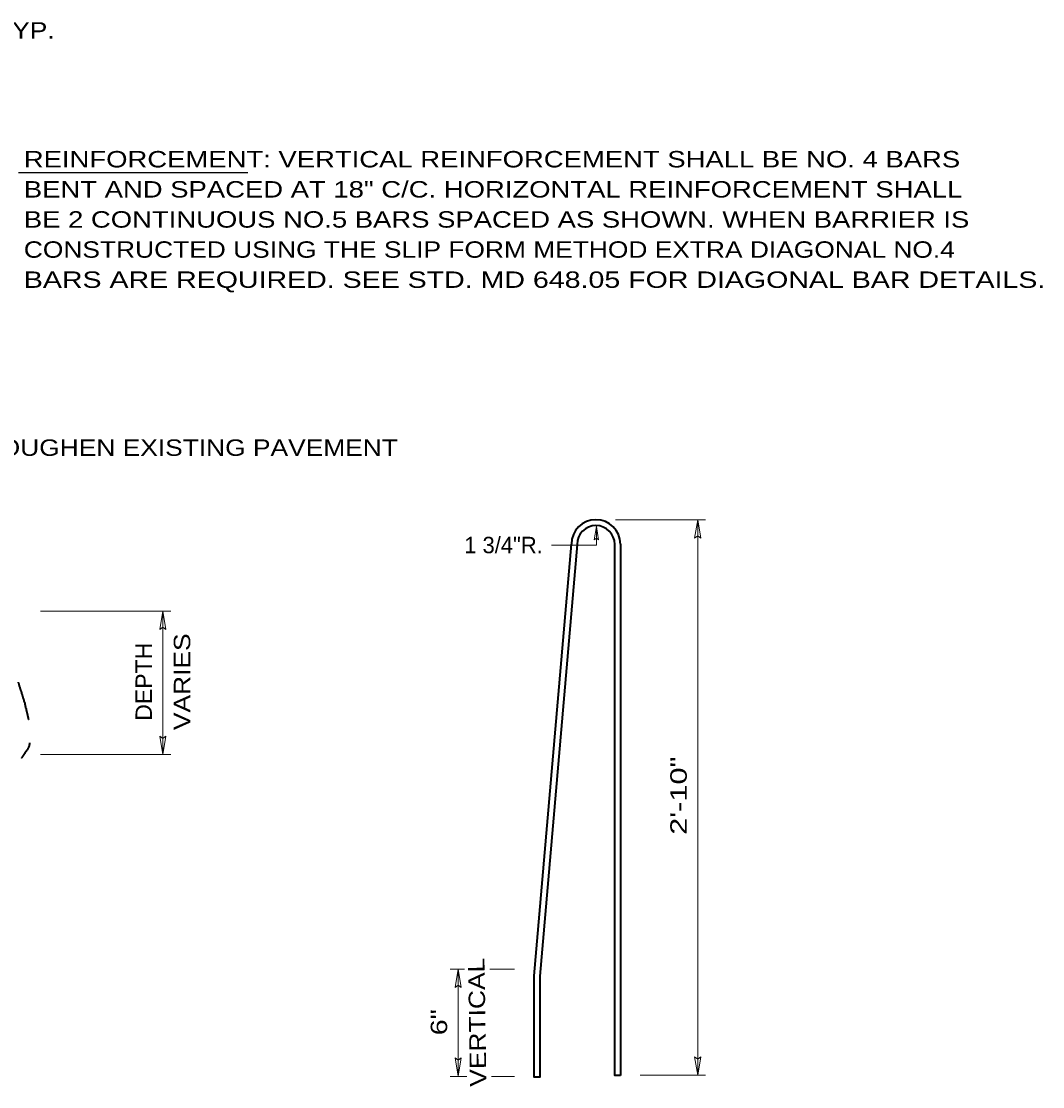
# Model space of a CAD drawing. Extents: x 2.21 to 9.21, y 11.59 to 21.05.
# Drawn here: x 5.477 to 9.21, y 16.167 to 20.059 of the extents above; entities that cross this region are included whole.
import ezdxf
from ezdxf.enums import TextEntityAlignment as Align

# ---------------------------------------------------------------- set-up
doc = ezdxf.new("R2010")
doc.units = 0
doc.header["$LTSCALE"] = 0.024
doc.linetypes.add('LONG_DASHED', pattern=[7.5, 6, -1.5])
for name, color, linetype, lineweight in [('1', 7, 'Continuous', 35), ('10', 7, 'Continuous', 13), ('12', 7, 'Continuous', 53)]:
    doc.layers.add(name, color=color, linetype=linetype, lineweight=lineweight)

msp = doc.modelspace()

# ---------------------------------------------------------------- linework, layer by layer
at = {"layer": '1'}
for p, q in [((7.35233, 16.57133), (7.488, 18.14917)), ((7.66683, 18.14917), (7.66683, 16.208))]:
    msp.add_line(p, q, dxfattribs=at)
for points in [[(7.50867, 18.14833), (7.373, 16.57083), (7.373, 16.201)], [(7.66683, 16.20717), (7.64617, 16.20717), (7.64617, 18.14833)], [(7.373, 16.2015), (7.35233, 16.2015), (7.35233, 16.57133)]]:
    msp.add_lwpolyline(points, dxfattribs=at)
for centre, radius in [((7.57745, 18.14914), 0.08937), ((7.57745, 18.14829), 0.06877)]:
    msp.add_arc(centre, radius, 0, 180, dxfattribs=at)
at = {"layer": '10', "lineweight": 25}
msp.add_line((5.46717, 19.5075), (6.30483, 19.5075), dxfattribs=at)
at = {"layer": '10'}
for p, q in [((7.6495, 18.23817), (7.97817, 18.23817)), ((7.93817, 18.17083), (7.9495, 18.23817)), ((7.9495, 18.23817), (7.9495, 16.20917)), ((7.96067, 18.17083), (7.9495, 18.23817)), ((7.57117, 18.16517), (7.57917, 18.21317)), ((7.58717, 18.16517), (7.57917, 18.21317)), ((7.93817, 18.17083), (7.9495, 18.17933)), ((7.96067, 18.17083), (7.9495, 18.17933)), ((7.57117, 18.16517), (7.57917, 18.17117)), ((7.58717, 18.16517), (7.57917, 18.17117)), ((5.548, 17.90433), (6.0235, 17.90433)), ((5.9835, 17.83717), (5.99467, 17.90433)), ((5.99467, 17.90433), (5.99467, 17.38)), ((6.006, 17.83717), (5.99467, 17.90433)), ((5.9835, 17.83717), (5.99467, 17.8455)), ((6.006, 17.83717), (5.99467, 17.8455)), ((5.9835, 17.44717), (5.99467, 17.38)), ((5.9835, 17.44717), (5.99467, 17.43883)), ((6.006, 17.44717), (5.99467, 17.38)), ((6.006, 17.44717), (5.99467, 17.43883)), ((5.548, 17.38), (6.0235, 17.38)), ((7.09683, 16.59633), (7.04483, 16.59633)), ((7.0625, 16.52917), (7.07367, 16.59633)), ((7.07367, 16.59633), (7.07367, 16.20533)), ((7.08483, 16.52917), (7.07367, 16.59633)), ((7.28033, 16.59633), (7.19017, 16.59633)), ((7.0625, 16.52917), (7.07367, 16.5375)), ((7.08483, 16.52917), (7.07367, 16.5375)), ((7.0625, 16.2725), (7.07367, 16.20533)), ((7.0625, 16.2725), (7.07367, 16.264)), ((7.08483, 16.2725), (7.07367, 16.20533)), ((7.08483, 16.2725), (7.07367, 16.264)), ((7.93817, 16.27633), (7.9495, 16.20917)), ((7.93817, 16.27633), (7.9495, 16.26783)), ((7.96067, 16.27633), (7.9495, 16.20917)), ((7.96067, 16.27633), (7.9495, 16.26783)), ((7.106, 16.204), (7.04483, 16.204)), ((7.28033, 16.204), (7.19633, 16.204)), ((7.73883, 16.20917), (7.97817, 16.20917))]:
    msp.add_line(p, q, dxfattribs=at)
msp.add_lwpolyline([(7.415, 18.14583), (7.57917, 18.14583), (7.57917, 18.21317)], dxfattribs=at)
at = {"layer": '10', "linetype": 'LONG_DASHED', "lineweight": 35}
for points in [[(5.466, 17.64517), (5.466, 17.64367), (5.467, 17.64067), (5.4675, 17.63967), (5.468, 17.63817), (5.468, 17.63667), (5.4685, 17.63517), (5.46883, 17.63417), (5.46983, 17.63133), (5.46983, 17.62983), (5.47083, 17.62733), (5.47183, 17.62433), (5.47267, 17.621), (5.47317, 17.61933), (5.47417, 17.6175), (5.47517, 17.614), (5.476, 17.6125), (5.477, 17.6095), (5.4775, 17.6075), (5.478, 17.6045), (5.4785, 17.60267), (5.48033, 17.59817), (5.48083, 17.59617), (5.48133, 17.59467), (5.48183, 17.59267), (5.48233, 17.59117), (5.48317, 17.58883), (5.48317, 17.58783), (5.48367, 17.58633), (5.48467, 17.58433), (5.48517, 17.58283), (5.48517, 17.58133), (5.48617, 17.57983), (5.48617, 17.57833), (5.488, 17.5725), (5.489, 17.57), (5.49, 17.5675), (5.49, 17.5655), (5.4905, 17.564), (5.49083, 17.562), (5.49133, 17.5605), (5.49133, 17.55917), (5.49183, 17.55667), (5.49283, 17.55517), (5.49283, 17.55317), (5.49333, 17.54967), (5.49467, 17.54767), (5.49467, 17.54633), (5.49517, 17.54483), (5.49567, 17.54133), (5.49617, 17.54033), (5.49667, 17.53733), (5.49717, 17.53583), (5.49767, 17.5325), (5.4985, 17.531), (5.4985, 17.5295), (5.499, 17.527), (5.5, 17.524), (5.5, 17.52267), (5.50133, 17.51817), (5.50133, 17.51617), (5.50183, 17.51517), (5.50183, 17.51417), (5.50233, 17.51267), (5.50233, 17.51117), (5.50283, 17.50933), (5.50333, 17.50833), (5.50283, 17.50783), (5.50383, 17.50633), (5.50383, 17.50483), (5.50433, 17.50333), (5.50433, 17.50183), (5.50517, 17.49883), (5.50483, 17.4975), (5.50567, 17.4945), (5.50617, 17.4935), (5.50617, 17.4925), (5.50667, 17.491), (5.50667, 17.48317), (5.50717, 17.48167), (5.50717, 17.46983), (5.50767, 17.4685), (5.50767, 17.4625), (5.508, 17.461), (5.508, 17.45267), (5.5085, 17.45117), (5.5085, 17.44783), (5.508, 17.44483), (5.5085, 17.44333), (5.5085, 17.44033), (5.5085, 17.4325), (5.508, 17.43117), (5.5085, 17.42967), (5.5085, 17.42817), (5.508, 17.42667), (5.508, 17.42467), (5.50767, 17.42333)], [(5.50767, 17.42333), (5.50767, 17.42183), (5.50717, 17.41983), (5.50717, 17.41833), (5.50617, 17.4155), (5.50617, 17.414), (5.50417, 17.40817), (5.50283, 17.40483), (5.50133, 17.40333), (5.50033, 17.40033), (5.4995, 17.3995), (5.4995, 17.398), (5.498, 17.396), (5.4965, 17.39567), (5.496, 17.39417), (5.49467, 17.39217), (5.49367, 17.39117), (5.49317, 17.39033), (5.49233, 17.38933), (5.49183, 17.38833), (5.49083, 17.38783), (5.48983, 17.385), (5.4885, 17.3835), (5.4875, 17.38167), (5.4865, 17.38117), (5.486, 17.37967), (5.48467, 17.37783), (5.48367, 17.37683), (5.48417, 17.37633), (5.48317, 17.37483), (5.48217, 17.37383), (5.48217, 17.37333), (5.48117, 17.372), (5.47933, 17.3695), (5.47833, 17.36817), (5.47783, 17.36767)]]:
    msp.add_spline(points, degree=3, dxfattribs=at)

# ---------------------------------------------------------------- texts
at = {"layer": '12'}
for s, width, p in [('3/4" R. TYP.', 1.2, (5.06725, 19.99608)), ('REINFORCEMENT: VERTICAL REINFORCEMENT SHALL BE NO. 4 BARS', 1.25, (5.4865, 19.52542)), ('BENT AND SPACED AT 18" C/C. HORIZONTAL REINFORCEMENT SHALL', 1.25, (5.4865, 19.41542)), ('BE 2 CONTINUOUS NO.5 BARS SPACED AS SHOWN. WHEN BARRIER IS', 1.25, (5.4865, 19.30542)), ('CONSTRUCTED USING THE SLIP FORM METHOD EXTRA DIAGONAL NO.4', 1.2, (5.4865, 19.19542)), ('BARS ARE REQUIRED. SEE STD. MD 648.05 FOR DIAGONAL BAR DETAILS.', 1.3, (5.4865, 19.08542)), ('ROUGHEN EXISTING PAVEMENT', 1.2, (5.32883, 18.47167))]:
    msp.add_text(s, height=0.06001, dxfattribs=dict(at, width=width)).set_placement(p)
msp.add_text('1 3/4"R.', height=0.06001, dxfattribs=at).set_placement((7.38333, 18.11583), align=Align.RIGHT)
for s, rotation, width, p in [('VARIES', 90, 1.2, (6.09467, 17.64629)), ('DEPTH', 90, 1.05, (5.95467, 17.64637)), ('2\'-10"', 90, 1.4, (7.90933, 17.23004)), ('VERTICAL', 90.938, 1.2, (7.17363, 16.40284)), ('6"', 90, 1.3, (7.03358, 16.40242))]:
    msp.add_text(s, height=0.06001, rotation=rotation, dxfattribs=dict(at, width=width)).set_placement(p, align=Align.CENTER)

doc.saveas('drawing.dxf')
